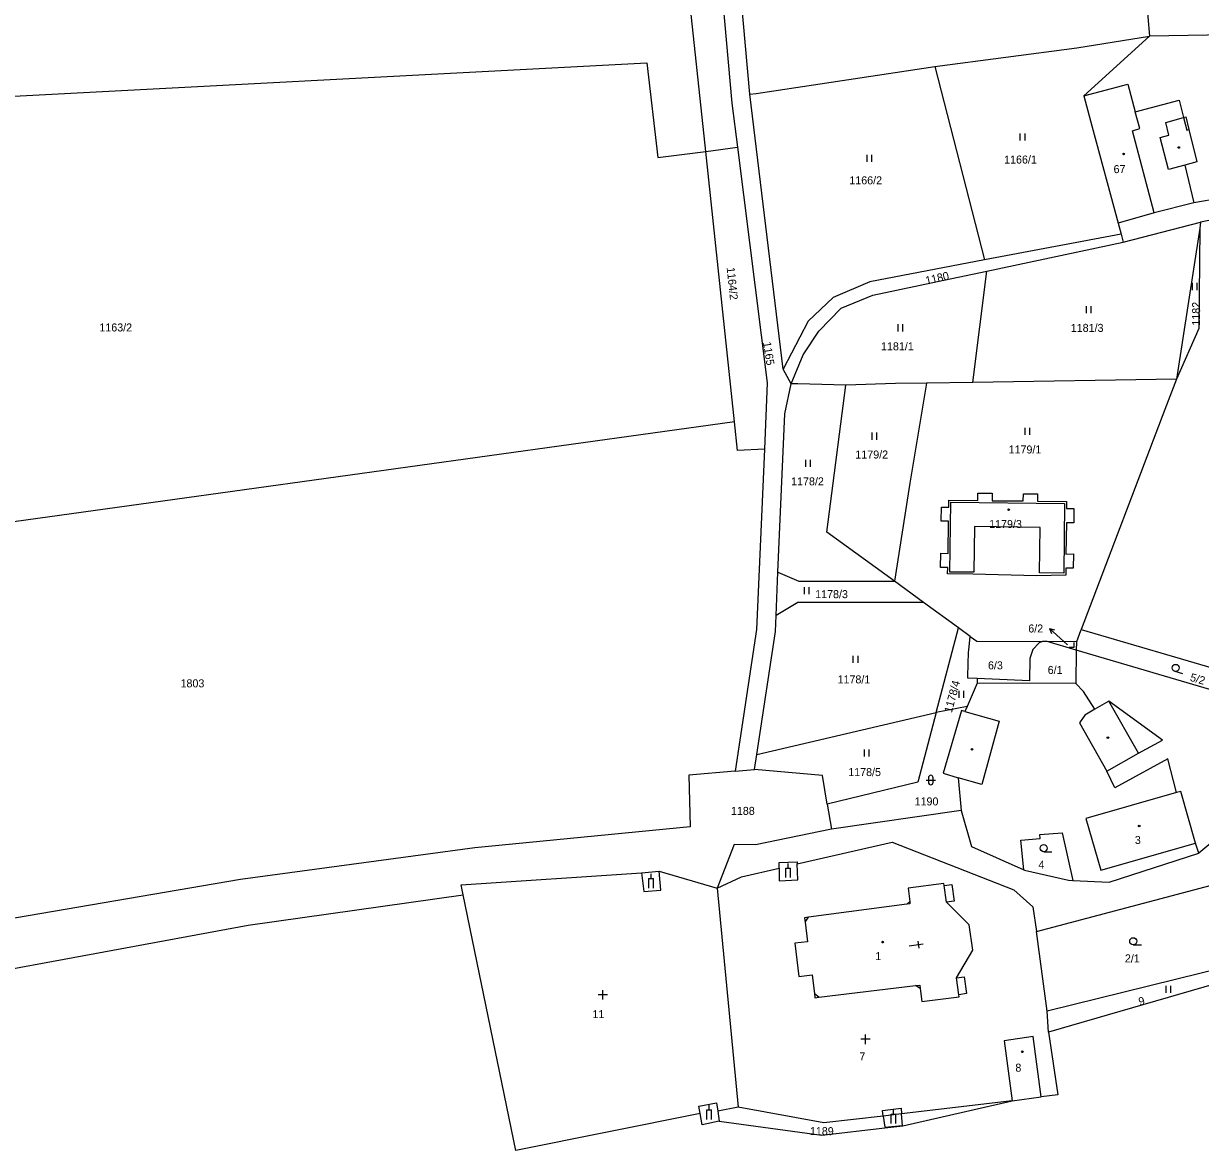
# Model space of a CAD drawing. Extents: x -520431 to -517205, y -1075927 to -1074013.
# Drawn here: x -518114.5 to -517864.6, y -1074514.5 to -1074275.3 of the extents above; entities that cross this region are included whole.
import ezdxf

# ---------------------------------------------------------------- set-up
doc = ezdxf.new("R2010")
doc.units = 0
for name, color, linetype in [('Hranice parcel', 7, 'Continuous'), ('Parcelní čísla', 7, 'Continuous'), ('Pop  PČ popisy', 7, 'Continuous'), ('Vnitřní kresba', 7, 'Continuous'), ('Značky budov', 7, 'Continuous'), ('Značky kultur', 7, 'Continuous')]:
    doc.layers.add(name, color=color, linetype=linetype)

msp = doc.modelspace()

# ---------------------------------------------------------------- linework, layer by layer
at = {"layer": 'Hranice parcel'}
for p, q in [((-517960.26, -1074290.32), (-517963.68, -1074251.76)), ((-517876.49, -1074266.06), (-517875.4, -1074277.95)), ((-517875.4, -1074277.95), (-517889.34, -1074290.65)), ((-517842.11, -1074277.41), (-517875.4, -1074277.95)), ((-517921.01, -1074284.42), (-517910.45, -1074325.49)), ((-517889.34, -1074290.65), (-517880.04, -1074288.16)), ((-517880.04, -1074288.16), (-517878.45, -1074294.01)), ((-517953.23, -1074348.65), (-517960.26, -1074290.32)), ((-517969.62, -1074302.45), (-517962.91, -1074301.55)), ((-517963.5, -1074359.86), (-517969.62, -1074302.45)), ((-517865.37, -1074304.66), (-517867.93, -1074305.35)), ((-517867.93, -1074305.35), (-517866.03, -1074313.38)), ((-517866.03, -1074313.38), (-517874.39, -1074315.47)), ((-517843.29, -1074313.21), (-517864.61, -1074317.45)), ((-517874.39, -1074315.47), (-517882.07, -1074317.7)), ((-517882.07, -1074317.7), (-517881.45, -1074319.99)), ((-517881, -1074321.68), (-517864.61, -1074317.45)), ((-517864.7, -1074318.74), (-517869.66, -1074350.77)), ((-517864.61, -1074317.45), (-517864.7, -1074318.74)), ((-517881.45, -1074319.99), (-517910.45, -1074325.49)), ((-517881.45, -1074319.99), (-517881, -1074321.68)), ((-517909.96, -1074327.84), (-517881, -1074321.68)), ((-517912.9, -1074351.47), (-517909.96, -1074327.84)), ((-517951.52, -1074351.77), (-517953.23, -1074348.65)), ((-517912.9, -1074351.47), (-517922.76, -1074351.63)), ((-517869.66, -1074350.77), (-517912.9, -1074351.47)), ((-517954.7, -1074400.93), (-517954.3, -1074391.76)), ((-517923.42, -1074398.16), (-517929.58, -1074393.68)), ((-517915.99, -1074403.58), (-517923.42, -1074398.16)), ((-517920.7, -1074421.52), (-517915.99, -1074403.58)), ((-517913.49, -1074405.4), (-517915.99, -1074403.58)), ((-517889.95, -1074403.92), (-517844.24, -1074417.35)), ((-517897.16, -1074406.49), (-517898.16, -1074406.49)), ((-517890.95, -1074408.31), (-517897.16, -1074406.49)), ((-517890.93, -1074406.51), (-517897.16, -1074406.49)), ((-517890.93, -1074406.51), (-517890.95, -1074408.31)), ((-517890.95, -1074408.31), (-517891.04, -1074415.38)), ((-517844.23, -1074422.04), (-517890.95, -1074408.31)), ((-517912, -1074415.34), (-517914.14, -1074420.25)), ((-517912.01, -1074414.36), (-517912, -1074415.34)), ((-517891.04, -1074415.38), (-517912, -1074415.34)), ((-517958.81, -1074430.48), (-517920.7, -1074421.52)), ((-517914.14, -1074420.25), (-517920.7, -1074421.52)), ((-517884.02, -1074419.14), (-517887.03, -1074420.86)), ((-517959.29, -1074433.66), (-517958.81, -1074430.48)), ((-517884.45, -1074433.97), (-517877.72, -1074430.16)), ((-517963.39, -1074434), (-517959.29, -1074433.66)), ((-517844.21, -1074434.05), (-517864.96, -1074451.42)), ((-517868.76, -1074438.28), (-517869.67, -1074438.54)), ((-517943.82, -1074441.02), (-517942.95, -1074446.28)), ((-517915.43, -1074442.37), (-517942.95, -1074446.28)), ((-517915.43, -1074442.37), (-517913.22, -1074449.99)), ((-517913.22, -1074449.99), (-517902.12, -1074454.95)), ((-517883.97, -1074457.59), (-517864.96, -1074451.42)), ((-517902.12, -1074454.95), (-517901.93, -1074455.04)), ((-517901.93, -1074455.04), (-517892.58, -1074457.17)), ((-517967.23, -1074458.86), (-517962.76, -1074505.29)), ((-517899.43, -1074468.03), (-517861.21, -1074457.92)), ((-517892.58, -1074457.17), (-517891.68, -1074457.21)), ((-517891.68, -1074457.21), (-517883.97, -1074457.59)), ((-517897.17, -1074484.93), (-517899.43, -1074468.03)), ((-517841.4, -1074473.36), (-517896.89, -1074489.41)), ((-517856.71, -1074474.95), (-517897.17, -1074484.93)), ((-517896.89, -1074489.41), (-517897.17, -1074484.93)), ((-517904.59, -1074504.01), (-517898.42, -1074503.16))]:
    msp.add_line(p, q, dxfattribs=at)
for points in [[(-517969.62, -1074302.45), (-517973.51, -1074266.04), (-517973.88, -1074184.44)], [(-517967.62, -1074252.6), (-517964.09, -1074292.2), (-517962.91, -1074301.55)], [(-517921.01, -1074284.42), (-517890.85, -1074280.45), (-517875.4, -1074277.95)], [(-518221.87, -1074296.35), (-518130.08, -1074291.45), (-517982.16, -1074283.63), (-517979.79, -1074303.75), (-517969.62, -1074302.45)], [(-517960.26, -1074290.32), (-517958.94, -1074290.12), (-517921.01, -1074284.42)], [(-517889.34, -1074290.65), (-517887.64, -1074297.04), (-517882.07, -1074317.7)], [(-517878.45, -1074294.01), (-517869.11, -1074291.57), (-517868.17, -1074295.26)], [(-517868.17, -1074295.26), (-517867.72, -1074295.13), (-517867.06, -1074297.8), (-517865.37, -1074304.66)], [(-517962.91, -1074301.55), (-517956.57, -1074351.59), (-517957.18, -1074365.67)], [(-517842.64, -1074310.06), (-517860.23, -1074312.36), (-517866.03, -1074313.38)], [(-517864.7, -1074318.74), (-517864.91, -1074340.02), (-517869.66, -1074350.77)], [(-517910.45, -1074325.49), (-517934.79, -1074330.1), (-517942.55, -1074333.45), (-517947.88, -1074338.47), (-517953.23, -1074348.65)], [(-517951.52, -1074351.77), (-517948.94, -1074345.62), (-517945.59, -1074340.6), (-517940.88, -1074335.73), (-517934.19, -1074332.99), (-517919.08, -1074329.78), (-517909.96, -1074327.84)], [(-517869.66, -1074350.77), (-517872.13, -1074357.24), (-517889.95, -1074403.92)], [(-517954.3, -1074391.76), (-517952.83, -1074358.14), (-517951.52, -1074351.77)], [(-517939.87, -1074352.03), (-517950.11, -1074351.8), (-517951.52, -1074351.77)], [(-517929.58, -1074393.68), (-517943.89, -1074383.25), (-517939.87, -1074352.03)], [(-517922.76, -1074351.63), (-517929.32, -1074351.74), (-517939.87, -1074352.03)], [(-517922.76, -1074351.63), (-517926.33, -1074372.87), (-517929.58, -1074393.68)], [(-517963.5, -1074359.86), (-518084.95, -1074376.67), (-518206.41, -1074393.49)], [(-517957.18, -1074365.67), (-517962.88, -1074365.9), (-517963.5, -1074359.86)], [(-517957.18, -1074365.67), (-517958.84, -1074403.95), (-517963.39, -1074434)], [(-517919.77, -1074390.74), (-517919.74, -1074387.74), (-517918.17, -1074387.76), (-517918.1, -1074380.96), (-517919.66, -1074380.94), (-517919.59, -1074377.95), (-517918.03, -1074377.95), (-517918.03, -1074376.5), (-517911.86, -1074376.55), (-517911.83, -1074375.01), (-517908.84, -1074375.02), (-517908.85, -1074376.59), (-517902.23, -1074376.63), (-517902.15, -1074375.11), (-517899.18, -1074375.14), (-517899.17, -1074376.7), (-517893.02, -1074376.75), (-517893.07, -1074378.22), (-517891.51, -1074378.22), (-517891.51, -1074381.25), (-517893.07, -1074381.25), (-517893.15, -1074387.9), (-517891.58, -1074387.89), (-517891.62, -1074390.88), (-517893.15, -1074390.92), (-517893.16, -1074392.42), (-517899.37, -1074392.53), (-517912.91, -1074392.2), (-517918.27, -1074392.13), (-517918.22, -1074390.78), (-517919.77, -1074390.74)], [(-517954.3, -1074391.76), (-517949.88, -1074393.66), (-517929.58, -1074393.68)], [(-517923.42, -1074398.16), (-517950.07, -1074398.17), (-517954.7, -1074400.93)], [(-517958.81, -1074430.48), (-517954.85, -1074404.32), (-517954.7, -1074400.93)], [(-517889.95, -1074403.92), (-517890.07, -1074404.24), (-517890.93, -1074406.51)], [(-517912.01, -1074414.36), (-517914.02, -1074414.28), (-517914, -1074413.8), (-517913.81, -1074408.72), (-517913.79, -1074408.28), (-517913.49, -1074405.4)], [(-517913.49, -1074405.4), (-517912.08, -1074406.43), (-517898.16, -1074406.49)], [(-517898.16, -1074406.49), (-517898.81, -1074406.76), (-517900.18, -1074408.2), (-517900.81, -1074410.11), (-517900.86, -1074414.83), (-517912.01, -1074414.36)], [(-517887.03, -1074420.86), (-517889.44, -1074417.09), (-517891.04, -1074415.38)], [(-517920.7, -1074421.52), (-517924.59, -1074436.32), (-517943.82, -1074441.02)], [(-517914.14, -1074420.25), (-517914.61, -1074421.32), (-517915.35, -1074421.1), (-517919.21, -1074434.44), (-517916.07, -1074435.38), (-517915.43, -1074442.37)], [(-517877.72, -1074430.16), (-517872.64, -1074427.4), (-517884.02, -1074419.14)], [(-517869.67, -1074438.54), (-517871.54, -1074431.38), (-517882.74, -1074437.5), (-517884.45, -1074433.97)], [(-517963.39, -1074434), (-517973.21, -1074434.83), (-517972.92, -1074445.78), (-518018.69, -1074450.3), (-518068.44, -1074456.97), (-518185.15, -1074476.95), (-518193.82, -1074470.98)], [(-517943.82, -1074441.02), (-517944.83, -1074434.89), (-517959.29, -1074433.66)], [(-517864.96, -1074451.42), (-517865.65, -1074449.29), (-517868.76, -1074438.28)], [(-517942.95, -1074446.28), (-517959.05, -1074449.66), (-517963.63, -1074449.54), (-517967.23, -1074458.86)], [(-517902.12, -1074454.95), (-517902.75, -1074448.63), (-517898.63, -1074448.29), (-517898.7, -1074447.41), (-517893.98, -1074447.11), (-517891.68, -1074457.21)], [(-517967.23, -1074458.86), (-517962.04, -1074456.41), (-517954.02, -1074454.57), (-517954.02, -1074453.38), (-517950.25, -1074453.22), (-517950.23, -1074453.7), (-517930.07, -1074449.06), (-517904.2, -1074459.21), (-517900.21, -1074462.81), (-517899.43, -1074468.03)], [(-518021.12, -1074460.27), (-518021.56, -1074458.11), (-517983.29, -1074455.56), (-517979.53, -1074455.24), (-517967.23, -1074458.86)], [(-517912.93, -1074471.96), (-517913.71, -1074466.61), (-517918.55, -1074461.81), (-517919.01, -1074458.27), (-517919.05, -1074457.84), (-517926.69, -1074458.84), (-517926.32, -1074461.67), (-517926.27, -1074462.14), (-517926.95, -1074462.23), (-517947.81, -1074465.02), (-517948.66, -1074465.14), (-517948.55, -1074466.02), (-517948.02, -1074470.22), (-517950.73, -1074470.51), (-517949.85, -1074477.57), (-517947.06, -1074477.22), (-517946.55, -1074481.28), (-517946.45, -1074482.09), (-517945.65, -1074481.99), (-517925.1, -1074479.51), (-517924.2, -1074479.41), (-517924.1, -1074480.15), (-517923.75, -1074482.87), (-517915.85, -1074481.89), (-517915.9, -1074481.45), (-517916.37, -1074477.86), (-517912.93, -1074471.96)], [(-518188.23, -1074498.93), (-518182.45, -1074487.55), (-518157.28, -1074487.29), (-518128.17, -1074478.03), (-518066.82, -1074466.68), (-518021.12, -1074460.27)], [(-517966.78, -1074508.32), (-517970.42, -1074509.06), (-517970.81, -1074506.64), (-518009.94, -1074514.51), (-518021.12, -1074460.27)], [(-517898.42, -1074503.16), (-517900.14, -1074490.35), (-517906.28, -1074491.25), (-517904.59, -1074504.01)], [(-517896.89, -1074489.41), (-517894.87, -1074502.73), (-517898.42, -1074503.16)], [(-517966.78, -1074508.32), (-517944.96, -1074511.24), (-517931.6, -1074509.73), (-517927.77, -1074509.26), (-517904.59, -1074504.01)], [(-517904.59, -1074504.01), (-517928.05, -1074506.75), (-517931.93, -1074507.2), (-517944.58, -1074508.68), (-517962.76, -1074505.29)], [(-517962.76, -1074505.29), (-517967.08, -1074506.17), (-517966.78, -1074508.32)]]:
    msp.add_lwpolyline(points, dxfattribs=at)
at = {"layer": 'Pop  PČ popisy'}
for p, q in [((-517894.41, -1074405.73), (-517896.64, -1074403.72)), ((-517896.64, -1074403.72), (-517895.56, -1074404.02)), ((-517896.64, -1074403.72), (-517896.23, -1074404.76)), ((-517892.82, -1074407.16), (-517894.41, -1074405.73))]:
    msp.add_line(p, q, dxfattribs=at)
at = {"layer": 'Vnitřní kresba'}
for p, q in [((-517877.47, -1074297.61), (-517878.45, -1074294.01)), ((-517871.96, -1074296.33), (-517868.17, -1074295.26)), ((-517871.28, -1074298.97), (-517871.96, -1074296.33)), ((-517868.17, -1074295.26), (-517867.5, -1074297.9)), ((-517879.05, -1074298.04), (-517877.47, -1074297.61)), ((-517874.39, -1074315.47), (-517879.05, -1074298.04)), ((-517873.13, -1074299.46), (-517871.28, -1074298.97)), ((-517867.5, -1074297.9), (-517867.06, -1074297.8)), ((-517871.36, -1074306.28), (-517873.13, -1074299.46)), ((-517867.93, -1074305.35), (-517871.36, -1074306.28)), ((-517917.8, -1074391.73), (-517917.61, -1074376.92)), ((-517917.61, -1074376.92), (-517893.46, -1074377.18)), ((-517893.46, -1074377.18), (-517893.63, -1074391.97)), ((-517912.57, -1074382.09), (-517912.68, -1074391.78)), ((-517898.63, -1074382.25), (-517912.57, -1074382.09)), ((-517898.76, -1074391.91), (-517898.63, -1074382.25)), ((-517912.68, -1074391.78), (-517917.8, -1074391.73)), ((-517893.63, -1074391.97), (-517898.76, -1074391.91)), ((-517914.61, -1074421.32), (-517907.32, -1074423.41)), ((-517887.03, -1074420.86), (-517889.17, -1074422.09)), ((-517877.72, -1074430.16), (-517884.02, -1074419.14)), ((-517907.32, -1074423.41), (-517911.04, -1074436.8)), ((-517889.17, -1074422.09), (-517890.26, -1074423.72)), ((-517890.26, -1074423.72), (-517884.45, -1074433.97)), ((-517911.04, -1074436.8), (-517916.07, -1074435.38)), ((-517869.67, -1074438.54), (-517888.93, -1074444.02)), ((-517888.93, -1074444.02), (-517885.75, -1074455.04)), ((-517885.75, -1074455.04), (-517865.65, -1074449.29)), ((-517950.09, -1074457.08), (-517950.23, -1074453.7)), ((-517983.29, -1074455.56), (-517982.81, -1074459.51)), ((-517979.19, -1074459.25), (-517979.53, -1074455.24)), ((-517954.02, -1074454.57), (-517954.03, -1074457.25)), ((-517954.03, -1074457.25), (-517950.09, -1074457.08)), ((-517919.01, -1074458.27), (-517917.35, -1074458.07)), ((-517917.35, -1074458.07), (-517916.89, -1074461.6)), ((-517982.81, -1074459.51), (-517979.19, -1074459.25)), ((-517926.95, -1074462.23), (-517926.32, -1074461.67)), ((-517916.89, -1074461.6), (-517918.55, -1074461.81)), ((-517948.55, -1074466.02), (-517947.81, -1074465.02)), ((-517916.37, -1074477.86), (-517914.74, -1074477.65)), ((-517914.74, -1074477.65), (-517914.28, -1074481.2)), ((-517945.65, -1074481.99), (-517946.55, -1074481.28)), ((-517924.1, -1074480.15), (-517925.1, -1074479.51)), ((-517914.28, -1074481.2), (-517915.9, -1074481.45)), ((-517971.12, -1074505.13), (-517967.33, -1074504.41)), ((-517970.81, -1074506.64), (-517971.12, -1074505.13)), ((-517967.33, -1074504.41), (-517967.08, -1074506.17)), ((-517932.07, -1074506.02), (-517928.14, -1074505.55)), ((-517931.93, -1074507.2), (-517932.07, -1074506.02)), ((-517928.14, -1074505.55), (-517928.05, -1074506.75)), ((-517931.93, -1074507.2), (-517931.64, -1074509.6)), ((-517927.87, -1074509.18), (-517928.05, -1074506.75)), ((-517931.64, -1074509.6), (-517927.87, -1074509.18))]:
    msp.add_line(p, q, dxfattribs=at)
at = {"layer": 'Značky budov'}
for p, q in [((-517923.5, -1074470.69), (-517926.46, -1074471.16)), ((-517924.6, -1074470.11), (-517924.37, -1074471.59))]:
    msp.add_line(p, q, dxfattribs=at)
for centre in [(-517869.2, -1074301.61), (-517880.91, -1074302.98), (-517905.32, -1074378.5), (-517884.25, -1074426.89), (-517913.11, -1074429.36), (-517877.6, -1074445.62), (-517932.07, -1074470.28), (-517902.43, -1074493.57)]:
    msp.add_circle(centre, 0.175, dxfattribs=at)
at = {"layer": 'Značky kultur'}
for p, q in [((-517902.84, -1074300.14), (-517902.84, -1074298.64)), ((-517901.84, -1074300.14), (-517901.84, -1074298.64)), ((-517935.34, -1074304.67), (-517935.34, -1074303.17)), ((-517934.34, -1074304.67), (-517934.34, -1074303.17)), ((-517866.28, -1074331.87), (-517866.28, -1074330.37)), ((-517865.28, -1074331.87), (-517865.28, -1074330.37)), ((-517888.78, -1074336.76), (-517888.78, -1074335.26)), ((-517887.78, -1074336.76), (-517887.78, -1074335.26)), ((-517928.81, -1074340.64), (-517928.81, -1074339.14)), ((-517927.81, -1074340.64), (-517927.81, -1074339.14)), ((-517901.84, -1074362.62), (-517901.84, -1074361.12)), ((-517900.84, -1074362.62), (-517900.84, -1074361.12)), ((-517934.28, -1074363.63), (-517934.28, -1074362.13)), ((-517933.28, -1074363.63), (-517933.28, -1074362.13)), ((-517948.37, -1074369.42), (-517948.37, -1074367.92)), ((-517947.37, -1074369.42), (-517947.37, -1074367.92)), ((-517948.67, -1074396.42), (-517948.67, -1074394.92)), ((-517947.67, -1074396.42), (-517947.67, -1074394.92)), ((-517892.44, -1074407.65), (-517891.44, -1074407.65)), ((-517891.44, -1074407.65), (-517891.44, -1074406.65)), ((-517938.3, -1074411.02), (-517938.3, -1074409.52)), ((-517937.3, -1074411.02), (-517937.3, -1074409.52)), ((-517870.06, -1074412.8), (-517868.38, -1074413.28)), ((-517915.85, -1074418.44), (-517915.85, -1074416.94)), ((-517914.85, -1074418.44), (-517914.85, -1074416.94)), ((-517935.94, -1074430.87), (-517935.94, -1074429.37)), ((-517934.94, -1074430.87), (-517934.94, -1074429.37)), ((-517922.85, -1074435.88), (-517920.85, -1074435.88)), ((-517922.35, -1074435.38), (-517922.35, -1074436.38)), ((-517921.35, -1074436.38), (-517921.35, -1074435.38)), ((-517897.87, -1074451.09), (-517896.12, -1074451.09)), ((-517952.16, -1074454.59), (-517952.16, -1074453.59)), ((-517981.23, -1074456.8), (-517981.23, -1074455.8)), ((-517952.66, -1074454.59), (-517951.66, -1074454.59)), ((-517952.66, -1074456.59), (-517952.66, -1074454.59)), ((-517951.66, -1074456.59), (-517951.66, -1074454.59)), ((-517981.73, -1074456.8), (-517980.73, -1074456.8)), ((-517981.73, -1074458.8), (-517981.73, -1074456.8)), ((-517980.73, -1074458.8), (-517980.73, -1074456.8)), ((-517878.87, -1074470.85), (-517877.12, -1074470.85)), ((-517990.47, -1074481.47), (-517992.47, -1074481.47)), ((-517991.47, -1074482.47), (-517991.47, -1074480.47)), ((-517871.87, -1074481.03), (-517871.87, -1074479.53)), ((-517870.87, -1074481.03), (-517870.87, -1074479.53)), ((-517934.69, -1074490.92), (-517936.69, -1074490.92)), ((-517935.69, -1074491.92), (-517935.69, -1074489.92)), ((-517969.41, -1074505.92), (-517968.41, -1074505.92)), ((-517969.41, -1074507.92), (-517969.41, -1074505.92)), ((-517968.91, -1074505.92), (-517968.91, -1074504.92)), ((-517968.41, -1074507.92), (-517968.41, -1074505.92)), ((-517929.77, -1074506.79), (-517929.77, -1074505.79)), ((-517930.27, -1074506.79), (-517929.27, -1074506.79)), ((-517930.27, -1074508.79), (-517930.27, -1074506.79)), ((-517929.27, -1074508.79), (-517929.27, -1074506.79))]:
    msp.add_line(p, q, dxfattribs=at)
for centre in [(-517869.86, -1074412.08), (-517897.87, -1074450.34), (-517878.87, -1074470.1)]:
    msp.add_circle(centre, 0.75, dxfattribs=at)
for centre, start, end in [((-517921.85, -1074435.38), 0, 180), ((-517921.85, -1074436.38), 180, 359.9879)]:
    msp.add_arc(centre, 0.5, start, end, dxfattribs=at)

# ---------------------------------------------------------------- texts
at = {"layer": 'Parcelní čísla'}
for s, p in [('1166/1', (-517906.28, -1074305.02)), ('67', (-517883.04, -1074307.05)), ('1166/2', (-517939.15, -1074309.43)), ('1163/2', (-518098.39, -1074340.66)), ('1181/3', (-517892.13, -1074340.75)), ('1181/1', (-517932.42, -1074344.67)), ('1179/2', (-517937.87, -1074367.63)), ('1179/1', (-517905.33, -1074366.56)), ('1178/2', (-517951.51, -1074373.33)), ('1179/3', (-517909.46, -1074382.38)), ('1178/3', (-517946.4, -1074397.27)), ('6/2', (-517901.15, -1074404.56)), ('6/3', (-517909.71, -1074412.38)), ('1178/1', (-517941.65, -1074415.37)), ('6/1', (-517897.03, -1074413.36)), ('1803', (-518081.16, -1074416.21)), ('1178/5', (-517939.38, -1074435.04)), ('1190', (-517925.29, -1074441.27)), ('1188', (-517964.29, -1074443.28)), ('3', (-517878.52, -1074449.45)), ('4', (-517898.98, -1074454.67)), ('1', (-517933.63, -1074474.11)), ('2/1', (-517880.64, -1074474.59)), ('11', (-517993.69, -1074486.42)), ('7', (-517937.02, -1074495.4)), ('8', (-517903.89, -1074497.79)), ('1189', (-517947.52, -1074511.26))]:
    msp.add_text(s, height=1.7, dxfattribs=at).set_placement(p)
for s, rotation, p in [('1164/2', 276, (-517965.2, -1074327.11)), ('1180', 13, (-517922.78, -1074330.72)), ('1182', 90, (-517864.66, -1074339.43)), ('1165', 279, (-517957.48, -1074342.97)), ('5/2', 344, (-517866.93, -1074414.8)), ('1178/4', 75, (-517917.4, -1074421.73)), ('9', 15, (-517877.49, -1074483.78))]:
    msp.add_text(s, height=1.7, rotation=rotation, dxfattribs=at).set_placement(p)

doc.saveas('drawing.dxf')
